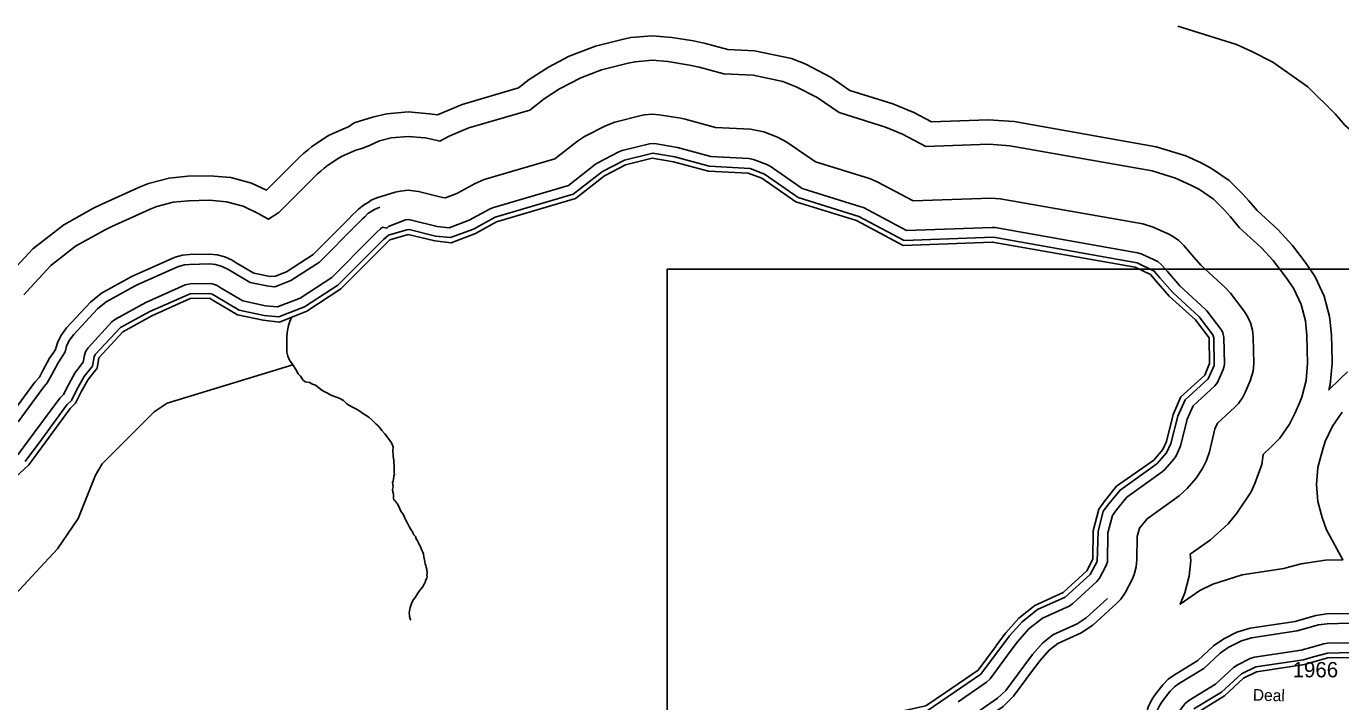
# Model space of a CAD drawing. Extents: x 2532689 to 2764727, y 536648 to 732970.
# Drawn here: x 2677109 to 2687851, y 585776 to 591292 of the extents above; entities that cross this region are included whole.
import ezdxf

# ---------------------------------------------------------------- set-up
doc = ezdxf.new("R2010")
doc.units = 0
for name, color, linetype in [('Exist Hydrographic Buffer Line', 7, 'Continuous'), ('Exist Hydrographic Creek Double Shore', 7, 'Continuous'), ('Exist Hydrographic Creek Single Shore', 7, 'Continuous'), ('Exist Road Secondary Type 51 Label', 7, 'Continuous'), ('Exist Road Secondary Type 51 Number Label', 7, 'Continuous'), ('Map Preparation Inset Cut Line', 7, 'Continuous')]:
    doc.layers.add(name, color=color, linetype=linetype)

msp = doc.modelspace()

# ---------------------------------------------------------------- linework, layer by layer
at = {"layer": 'Exist Hydrographic Buffer Line'}
for points in [[(2686519, 591293), (2686998, 591144), (2687124, 591087), (2687296, 590998), (2687582, 590798), (2687806, 590578), (2687856, 590521), (2687886, 590486), (2688020, 590365), (2688060, 590422), (2688306, 590669), (2688436, 590769), (2688510, 590821), (2688523, 590842), (2688612, 590960), (2688947, 591310)], [(2681131, 590789), (2681218, 590858), (2681376, 590959), (2681547, 591048), (2681762, 591130), (2681978, 591185), (2682049, 591200), (2682223, 591215), (2682386, 591202), (2682562, 591173), (2682661, 591151), (2682842, 591102), (2683060, 591091), (2683363, 591028), (2683473, 590986), (2683687, 590874), (2683840, 590768), (2684191, 590660), (2684362, 590588), (2684506, 590512), (2684970, 590529), (2685181, 590514), (2686344, 590308), (2686584, 590234), (2686710, 590177), (2686796, 590132), (2686939, 590032), (2687051, 589922), (2687100, 589866), (2687168, 589787), (2687339, 589631), (2687458, 589501), (2687570, 589355), (2687641, 589247), (2687715, 589089), (2687760, 588921), (2687775, 588771), (2687780, 588561), (2687780, 588537), (2687765, 588364), (2687754, 588323), (2687846, 588414), (2687906, 588471)], [(2677090, 589099), (2677114, 589127), (2677309, 589339), (2677511, 589497), (2677749, 589628), (2677808, 589657), (2678122, 589798), (2678176, 589820), (2678310, 589856), (2678434, 589868), (2678607, 589871), (2678746, 589859), (2678881, 589823), (2679016, 589759), (2679049, 589739), (2679088, 589716), (2679174, 589772), (2679441, 590039), (2679489, 590088), (2679516, 590110), (2679543, 590134), (2679570, 590155), (2679657, 590213), (2679685, 590229), (2679783, 590273), (2679811, 590282), (2679852, 590293), (2679913, 590320), (2679996, 590358), (2680090, 590381), (2680229, 590393), (2680368, 590381), (2680420, 590370), (2680490, 590353), (2680565, 590395), (2680726, 590462), (2681224, 590608), (2681341, 590701), (2681468, 590782), (2681640, 590871), (2681811, 590936), (2682027, 590991), (2682084, 591003), (2682223, 591015), (2682353, 591004), (2682529, 590975), (2682609, 590958), (2682811, 590904), (2683050, 590892), (2683292, 590841), (2683402, 590799), (2683573, 590710), (2683752, 590587), (2684132, 590469), (2684269, 590412), (2684460, 590310), (2684978, 590329), (2685146, 590317), (2686310, 590111), (2686502, 590052), (2686627, 589995), (2686696, 589959), (2686811, 589879), (2686900, 589791), (2686949, 589735)], [(2676967, 589263), (2677162, 589474), (2677415, 589672), (2677653, 589803), (2677726, 589840), (2678040, 589981), (2678107, 590008), (2678276, 590053), (2678430, 590068), (2678607, 590071), (2678781, 590056), (2678949, 590011), (2679072, 589953), (2679287, 590168), (2679348, 590229), (2679374, 590252), (2679415, 590287), (2679441, 590308), (2679558, 590386), (2679585, 590402), (2679715, 590460), (2679743, 590470), (2679789, 590504), (2679938, 590549), (2680056, 590578), (2680229, 590593), (2680403, 590578), (2680469, 590570), (2680670, 590654), (2681131, 590789)], [(2678442, 589428), (2678607, 589431), (2678670, 589426), (2678731, 589409), (2678791, 589381), (2678825, 589361), (2678968, 589276), (2679102, 589248), (2679146, 589252), (2679236, 589287), (2679453, 589428), (2679736, 589711), (2679779, 589755), (2679801, 589777), (2679824, 589799), (2679852, 589820), (2679874, 589838), (2679904, 589854), (2679928, 589871), (2679975, 589892), (2680124, 589937), (2680167, 589947), (2680229, 589953), (2680292, 589947), (2680315, 589943), (2680510, 589895), (2680535, 589892), (2680629, 589927), (2680778, 590009), (2680851, 590040), (2681429, 590210), (2681613, 590354), (2681670, 590391), (2681842, 590480), (2681919, 590509), (2682135, 590564), (2682161, 590570), (2682223, 590575), (2682282, 590570), (2682458, 590541), (2682493, 590534), (2682741, 590467), (2683027, 590452), (2683137, 590429), (2683247, 590388), (2683324, 590347), (2683558, 590186), (2684001, 590048), (2684063, 590023), (2684358, 589867), (2684993, 589889), (2685069, 589884), (2686233, 589678), (2686319, 589651), (2686445, 589594), (2686476, 589578), (2686528, 589542), (2686568, 589503), (2686616, 589447), (2686709, 589340), (2686906, 589159), (2686949, 589112), (2687061, 588966), (2687087, 588927), (2687114, 588870), (2687130, 588810), (2687135, 588756), (2687140, 588537), (2687135, 588475), (2687111, 588396), (2687071, 588302), (2687052, 588264), (2687016, 588212), (2686984, 588178), (2686844, 588050), (2686823, 588005), (2686778, 587818), (2686753, 587747), (2686721, 587680), (2686669, 587601), (2686597, 587516), (2686532, 587457), (2686269, 587270), (2686206, 587192), (2686188, 587124), (2686185, 586934), (2686180, 586877), (2686164, 586816), (2686146, 586775), (2686089, 586665), (2686053, 586614), (2686021, 586580), (2685826, 586401), (2685731, 586339), (2685540, 586252)], [(2677041, 587792), (2677171, 587969), (2677384, 588256), (2677412, 588284), (2677453, 588365), (2677509, 588465), (2677521, 588482), (2677574, 588550), (2677584, 588606), (2677590, 588626), (2677598, 588645), (2677614, 588666), (2677809, 588878), (2677839, 588901), (2678086, 589037), (2678408, 589181), (2678447, 589188), (2678607, 589191), (2678628, 589189), (2678648, 589184), (2678669, 589174), (2678702, 589154), (2678880, 589049), (2679064, 589010), (2679162, 589000), (2679234, 589028), (2679346, 589072), (2679605, 589241), (2679935, 589572), (2679971, 589608), (2680003, 589639), (2680020, 589651), (2680056, 589643), (2680070, 589657), (2680209, 589711), (2680229, 589713), (2680258, 589709), (2680468, 589658), (2680565, 589647), (2680729, 589708), (2680894, 589799), (2680918, 589809), (2681541, 589993), (2681761, 590166), (2681780, 590178), (2681952, 590267), (2681978, 590277), (2682203, 590333), (2682243, 590334), (2682431, 590302), (2682703, 590228), (2683015, 590212), (2683052, 590205), (2683162, 590163), (2683187, 590150), (2683451, 589968), (2683930, 589819), (2683951, 589811), (2684302, 589624), (2685002, 589650), (2685027, 589648), (2686191, 589442), (2686220, 589433), (2686356, 589370), (2686387, 589345), (2686435, 589290), (2686537, 589173), (2686744, 588982), (2686758, 588967), (2686879, 588807), (2686888, 588788), (2686895, 588750), (2686900, 588537), (2686899, 588516), (2686891, 588490)], [(2678661, 589086), (2678850, 588974), (2679052, 588931), (2679173, 588918), (2679263, 588954), (2679383, 589001), (2679656, 589178), (2680011, 589535), (2680028, 589551), (2680069, 589586), (2680218, 589631), (2680239, 589632), (2680454, 589579), (2680575, 589566), (2680763, 589635), (2680941, 589733), (2681579, 589921), (2681817, 590107), (2681998, 590199), (2682230, 590255), (2682410, 590225), (2682691, 590149), (2683024, 590130), (2683142, 590084), (2683416, 589895), (2683913, 589740), (2684284, 589544), (2685013, 589569), (2686187, 589360), (2686327, 589293), (2686374, 589238), (2686479, 589117), (2686695, 588918), (2686807, 588772), (2686815, 588748), (2686817, 588522), (2686767, 588414), (2686579, 588241), (2686519, 588108), (2686464, 587885), (2686427, 587809), (2686347, 587718), (2686048, 587505), (2685955, 587391), (2685911, 587331), (2685868, 587167), (2685861, 586921), (2685804, 586816), (2685599, 586630), (2685372, 586528), (2685248, 586429), (2685145, 586314), (2684911, 586001), (2684470, 585702)], [(2677042, 588063), (2677244, 588338), (2677281, 588379), (2677314, 588442), (2677370, 588543), (2677395, 588582), (2677427, 588633), (2677439, 588680), (2677460, 588725), (2677497, 588775), (2677692, 588986), (2677762, 589041), (2678000, 589173), (2678021, 589183), (2678335, 589323), (2678354, 589331), (2678401, 589344), (2678444, 589348), (2678607, 589351), (2678656, 589347), (2678703, 589334), (2678750, 589312), (2678784, 589292), (2678938, 589200), (2679089, 589169), (2679140, 589163), (2679175, 589177), (2679272, 589215), (2679504, 589366), (2679807, 589670), (2679841, 589704), (2679858, 589721), (2679876, 589737), (2679900, 589762), (2679956, 589797), (2679999, 589815)], [(2686949, 589735), (2687025, 589647), (2687203, 589484), (2687299, 589380), (2687411, 589233), (2687468, 589147), (2687527, 589021), (2687563, 588886), (2687575, 588766), (2687580, 588537), (2687568, 588398), (2687532, 588264), (2687516, 588223), (2687476, 588129), (2687433, 588044), (2687353, 587929), (2687281, 587854), (2687217, 587796), (2687206, 587714), (2687150, 587557), (2687118, 587490), (2687003, 587315), (2686930, 587229), (2686787, 587099), (2686621, 586980), (2686625, 586929), (2686613, 586800), (2686577, 586665), (2686539, 586572), (2686699, 586683), (2686806, 586737), (2687046, 586812), (2687386, 586863), (2687424, 586874), (2687529, 586903), (2687727, 586933), (2687869, 586936), (2687736, 587180), (2687700, 587281), (2687665, 587412), (2687653, 587551), (2687665, 587690), (2687690, 587790), (2687714, 587867), (2687725, 587901), (2687784, 588027), (2687864, 588142)], [(2676978, 588111), (2677180, 588385), (2677216, 588427), (2677244, 588481), (2677300, 588582), (2677333, 588632), (2677349, 588652), (2677364, 588708), (2677391, 588765), (2677438, 588829), (2677633, 589040), (2677724, 589112), (2677962, 589243), (2677988, 589256), (2678302, 589397), (2678326, 589406), (2678387, 589422), (2678442, 589428)], [(2677101, 587738), (2677235, 587921), (2677441, 588200), (2677478, 588236), (2677523, 588326), (2677583, 588432), (2677650, 588516), (2677663, 588592), (2677673, 588612), (2677878, 588831), (2678119, 588964), (2678449, 589108), (2678607, 589111), (2678628, 589105), (2678661, 589086)], [(2686891, 588490), (2686844, 588384), (2686821, 588355), (2686645, 588193), (2686595, 588083), (2686545, 587874), (2686537, 587851), (2686505, 587784), (2686487, 587757), (2686414, 587672), (2686393, 587653), (2686103, 587446), (2686019, 587343), (2685985, 587296), (2685948, 587156), (2685944, 586918), (2685932, 586884), (2685881, 586785), (2685858, 586757), (2685663, 586578), (2685632, 586557), (2685414, 586459), (2685303, 586371), (2685208, 586263), (2685129, 586157)], [(2685944, 586618), (2685772, 586460), (2685698, 586412), (2685498, 586321), (2685413, 586254)], [(2685901, 585601), (2686057, 585604), (2686120, 585599), (2686194, 585578), (2686230, 585563), (2686254, 585559), (2686256, 585620), (2686261, 585671), (2686277, 585731), (2686304, 585788), (2686329, 585827), (2686397, 585914), (2686441, 585959), (2686485, 585990), (2686684, 586112), (2686812, 586231), (2686896, 586290), (2687003, 586343), (2687111, 586377), (2687479, 586432), (2687543, 586450), (2687648, 586480), (2687737, 586493), (2687920, 586497)], [(2686034, 585524), (2686057, 585524), (2686106, 585520), (2686163, 585504), (2686235, 585483), (2686333, 585535), (2686336, 585617), (2686340, 585657), (2686352, 585704), (2686373, 585748), (2686393, 585778), (2686458, 585863), (2686492, 585897), (2686526, 585922), (2686732, 586048), (2686867, 586173), (2686932, 586218), (2687039, 586272), (2687123, 586298), (2687496, 586354), (2687564, 586373), (2687670, 586403), (2687739, 586413), (2687922, 586417)], [(2685413, 586254), (2685332, 586162), (2685260, 586065)], [(2685540, 586252), (2685469, 586196), (2685394, 586112), (2685325, 586019)], [(2686302, 585337), (2686446, 585413), (2686491, 585487), (2686497, 585629), (2686503, 585649), (2686520, 585681), (2686580, 585760), (2686610, 585785), (2686829, 585920), (2686976, 586056), (2687004, 586075), (2687111, 586129), (2687147, 586140), (2687529, 586197), (2687608, 586219), (2687713, 586249), (2687743, 586253), (2687944, 586256)], [(2685128, 586156), (2684985, 585963), (2684956, 585936), (2684724, 585776)], [(2686652, 585717), (2686878, 585855), (2687039, 586003), (2687158, 586061), (2687546, 586119), (2687629, 586142), (2687744, 586173), (2687934, 586177)], [(2685260, 586065), (2685113, 585868), (2685047, 585804), (2684866, 585679)], [(2685325, 586019), (2685178, 585820), (2685092, 585738), (2684929, 585626)]]:
    msp.add_lwpolyline(points, dxfattribs=at)
at = {"layer": 'Exist Hydrographic Creek Double Shore'}
for points in [[(2686344, 589211), (2686296, 589266), (2686170, 589324), (2685006, 589530), (2684274, 589503), (2683894, 589705), (2683398, 589859), (2683119, 590051), (2683009, 590093), (2682684, 590109), (2682399, 590186), (2682223, 590215), (2682007, 590160), (2681835, 590071), (2681597, 589885), (2680952, 589694), (2680779, 589599), (2680580, 589525), (2680447, 589539), (2680229, 589593), (2680080, 589547), (2680056, 589523)], [(2680056, 589523), (2679681, 589147), (2679401, 588965), (2679278, 588917)], [(2685030, 586226), (2685114, 586339), (2685220, 586458), (2685351, 586562), (2685582, 586667), (2685777, 586845), (2685825, 586939), (2685828, 587172), (2685874, 587348), (2685923, 587416), (2686020, 587535), (2686323, 587750), (2686396, 587836), (2686428, 587902), (2686481, 588121), (2686545, 588265), (2686740, 588444), (2686780, 588537), (2686775, 588747), (2686663, 588894), (2686450, 589089), (2686344, 589211)], [(2678641, 589051), (2678607, 589071), (2678449, 589068), (2678135, 588927), (2677897, 588796), (2677702, 588585), (2677687, 588499), (2677614, 588407), (2677558, 588306), (2677510, 588213), (2677469, 588171), (2677267, 587897), (2677130, 587711), (2676804, 587412), (2676740, 587297)], [(2679278, 588917), (2679178, 588877), (2679045, 588892), (2678835, 588936), (2678641, 589051)], [(2684622, 585852), (2684888, 586034), (2685030, 586225)], [(2686413, 585260), (2686530, 585323), (2686610, 585451), (2686615, 585608), (2686672, 585683), (2686902, 585823), (2687057, 585968), (2687164, 586021), (2687554, 586080), (2687640, 586104)], [(2687640, 586104), (2687745, 586133), (2687928, 586137)], [(2683677, 585231), (2683814, 585275), (2684041, 585590), (2684163, 585677), (2684461, 585741), (2684621, 585851)]]:
    msp.add_lwpolyline(points, dxfattribs=at)
at = {"layer": 'Exist Hydrographic Creek Single Shore'}
for points in [[(2679278, 588917), (2679272, 588903), (2679261, 588872), (2679252, 588848), (2679247, 588820), (2679240, 588789), (2679239, 588759), (2679238, 588737), (2679238, 588711), (2679239, 588687), (2679238, 588651), (2679239, 588631), (2679246, 588597), (2679261, 588566), (2679282, 588536), (2679287, 588528)], [(2680933, 585474), (2677842, 585455), (2677342, 585441), (2676991, 585476), (2676714, 585587), (2676535, 585724), (2676509, 585798), (2676513, 585930), (2676561, 586040), (2676737, 586352), (2677363, 587025), (2677532, 587271), (2677674, 587625), (2677730, 587719), (2678155, 588143), (2678261, 588213), (2679287, 588528)], [(2679287, 588528), (2679293, 588518), (2679311, 588489), (2679331, 588455), (2679349, 588434), (2679368, 588405), (2679389, 588389), (2679423, 588382), (2679449, 588369), (2679472, 588360), (2679496, 588342), (2679513, 588329), (2679533, 588315), (2679561, 588302), (2679606, 588278), (2679635, 588267), (2679665, 588255), (2679702, 588235), (2679728, 588209), (2679751, 588194), (2679775, 588181), (2679808, 588164), (2679834, 588148), (2679859, 588131), (2679879, 588120), (2679908, 588101), (2679937, 588076), (2679968, 588044), (2679982, 588031), (2680001, 588011), (2680015, 587992), (2680040, 587964), (2680067, 587929), (2680080, 587910), (2680093, 587890), (2680106, 587858), (2680105, 587826), (2680108, 587788), (2680108, 587778), (2680113, 587750), (2680114, 587728), (2680115, 587702), (2680116, 587674), (2680116, 587664), (2680116, 587646), (2680117, 587634), (2680113, 587620), (2680110, 587590), (2680107, 587576), (2680103, 587568), (2680106, 587530), (2680103, 587509), (2680105, 587491), (2680108, 587483), (2680110, 587468), (2680109, 587453), (2680109, 587435), (2680114, 587424), (2680120, 587418), (2680136, 587398), (2680143, 587392), (2680158, 587357), (2680170, 587333), (2680185, 587311), (2680196, 587292), (2680202, 587276), (2680211, 587258), (2680219, 587244), (2680226, 587229), (2680238, 587207), (2680249, 587189), (2680258, 587173), (2680262, 587168), (2680272, 587150), (2680277, 587140), (2680289, 587126), (2680296, 587106), (2680306, 587089), (2680315, 587073), (2680321, 587061), (2680327, 587049), (2680339, 587020), (2680349, 586996), (2680356, 586980), (2680358, 586960), (2680363, 586934), (2680370, 586902), (2680373, 586888), (2680377, 586876), (2680382, 586857), (2680385, 586827), (2680383, 586807), (2680384, 586797), (2680382, 586786), (2680374, 586772), (2680371, 586764), (2680371, 586758), (2680361, 586736), (2680346, 586711), (2680333, 586695)], [(2680333, 586695), (2680321, 586678), (2680308, 586662), (2680302, 586648), (2680291, 586631), (2680274, 586611), (2680266, 586598), (2680255, 586570), (2680245, 586544), (2680242, 586517), (2680239, 586497), (2680242, 586485), (2680242, 586479), (2680242, 586471), (2680246, 586453), (2680251, 586442)]]:
    msp.add_lwpolyline(points, dxfattribs=at)
at = {"layer": 'Map Preparation Inset Cut Line'}
msp.add_lwpolyline([(2682347, 562753), (2695930, 562753), (2695930, 589310), (2682347, 589310)], close=True, dxfattribs=at)

# ---------------------------------------------------------------- texts
at = {"layer": 'Exist Road Secondary Type 51 Label'}
msp.add_text('Deal', height=95, rotation=358.5521, dxfattribs=at).set_placement((2687132, 585785))
at = {"layer": 'Exist Road Secondary Type 51 Number Label'}
msp.add_text('1966', height=125, dxfattribs=at).set_placement((2687458, 585975))

doc.saveas('drawing.dxf')
